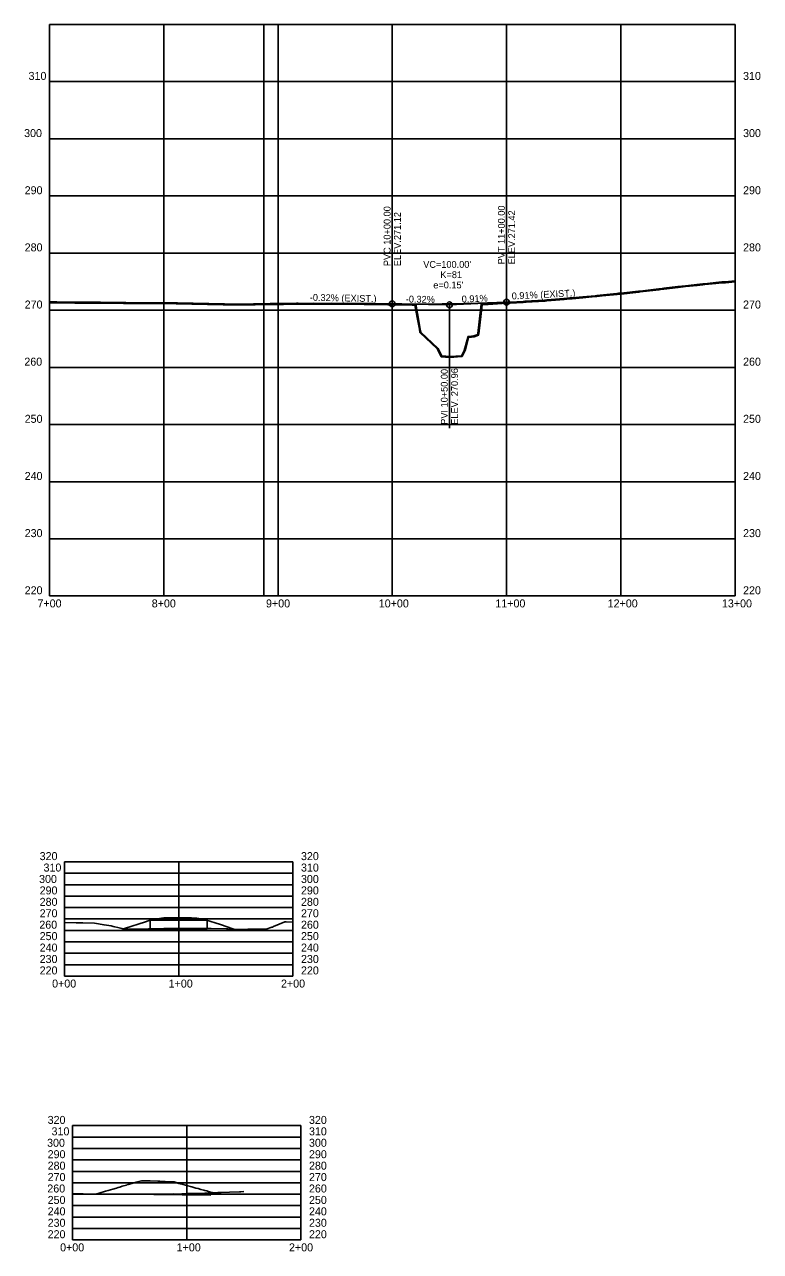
# Model space of a CAD drawing. Extents: x 1661035 to 1663788, y 668049 to 670894.
# Drawn here: x 1663144 to 1663788, y 669133 to 670207 of the extents above; entities that cross this region are included whole.
import ezdxf

# ---------------------------------------------------------------- set-up
doc = ezdxf.new("R2010")
doc.units = 0
for name, color, linetype in [('Default', 7, 'Continuous'), ('R_Axis', 7, 'Continuous'), ('R_Axis Annot', 7, 'Continuous'), ('R_Exist Surface', 7, 'Continuous'), ('R_Fin Surface', 7, 'Continuous'), ('R_Grid', 7, 'Continuous'), ('R_Horz Alg Annot', 7, 'Continuous'), ('R_Proposed Const Limits_Fill', 7, 'Continuous'), ('R_Vert Alg', 7, 'Continuous'), ('R_Vert Alg Annot', 7, 'Continuous'), ('R_Water', 7, 'Continuous')]:
    doc.layers.add(name, color=color, linetype=linetype)

msp = doc.modelspace()

# ---------------------------------------------------------------- linework, layer by layer
at = {"layer": 'Default'}
for p, q in [((1663600.6, 669965.7), (1663615.6, 669967)), ((1663165.4, 669964.1), (1663170.3, 669964)), ((1663170.3, 669964), (1663171.9, 669964)), ((1663171.9, 669964), (1663185.8, 669963.9)), ((1663185.8, 669963.9), (1663187.7, 669963.8)), ((1663187.7, 669963.8), (1663208.1, 669963.7)), ((1663208.1, 669963.7), (1663210, 669963.7)), ((1663210, 669963.7), (1663230.3, 669963.6)), ((1663230.3, 669963.6), (1663232.3, 669963.6)), ((1663232.3, 669963.6), (1663253.4, 669963.3)), ((1663253.4, 669963.3), (1663255.2, 669963.3)), ((1663255.2, 669963.3), (1663276.4, 669963.1)), ((1663276.4, 669963.1), (1663277.4, 669963.1)), ((1663277.4, 669963.1), (1663290, 669962.9)), ((1663290, 669962.9), (1663291.2, 669962.8)), ((1663291.2, 669962.8), (1663303.7, 669962.6)), ((1663303.7, 669962.6), (1663304.9, 669962.6)), ((1663304.9, 669962.6), (1663317.3, 669962.4)), ((1663317.3, 669962.4), (1663318.7, 669962.3)), ((1663318.7, 669962.3), (1663330.9, 669962.1)), ((1663330.9, 669962.1), (1663332.4, 669962.1)), ((1663332.4, 669962.1), (1663344, 669962.3)), ((1663344, 669962.3), (1663345.4, 669962.3)), ((1663345.4, 669962.3), (1663357, 669962.4)), ((1663357, 669962.4), (1663358.4, 669962.5)), ((1663358.4, 669962.5), (1663381.7, 669962.8)), ((1663381.7, 669962.8), (1663383.1, 669962.8)), ((1663383.1, 669962.8), (1663395.3, 669962.7)), ((1663395.3, 669962.7), (1663396.8, 669962.8)), ((1663396.8, 669962.8), (1663409, 669962.7)), ((1663409, 669962.7), (1663412, 669962.8)), ((1663412, 669962.8), (1663424.2, 669962.7)), ((1663424.2, 669962.7), (1663425.8, 669962.8)), ((1663425.8, 669962.8), (1663437.9, 669962.7)), ((1663437.9, 669962.7), (1663440.9, 669962.7)), ((1663440.9, 669962.7), (1663449.4, 669962.5)), ((1663449.4, 669962.5), (1663461.6, 669962.3)), ((1663461.6, 669962.3), (1663465.3, 669962.3)), ((1663465.3, 669962.3), (1663466.1, 669962.3)), ((1663466.1, 669962.3), (1663482.7, 669962)), ((1663482.7, 669962), (1663485.9, 669961.9)), ((1663485.9, 669961.9), (1663488.4, 669948.9)), ((1663540.3, 669936.3), (1663543.3, 669962)), ((1663543.3, 669962), (1663547.8, 669962.4)), ((1663547.8, 669962.4), (1663549.1, 669962.5)), ((1663549.1, 669962.5), (1663565.8, 669963.7)), ((1663565.8, 669963.7), (1663566.8, 669963.8)), ((1663566.8, 669963.8), (1663568.6, 669963.9)), ((1663568.6, 669963.9), (1663579.9, 669964.4)), ((1663579.9, 669964.4), (1663581.4, 669964.5)), ((1663581.4, 669964.5), (1663592.9, 669965.1)), ((1663592.9, 669965.1), (1663593.4, 669965.1)), ((1663593.4, 669965.1), (1663598.7, 669965.5)), ((1663598.7, 669965.5), (1663600.6, 669965.7)), ((1663488.4, 669948.9), (1663489.9, 669940.2)), ((1663489.9, 669940.2), (1663490.4, 669937.6)), ((1663490.4, 669937.6), (1663495.3, 669932.9)), ((1663532.5, 669933.7), (1663536.7, 669934.2)), ((1663536.7, 669934.2), (1663536.9, 669934.3)), ((1663536.9, 669934.3), (1663540.2, 669935.5)), ((1663540.2, 669935.5), (1663540.3, 669936.3)), ((1663495.3, 669932.9), (1663505.6, 669923.1)), ((1663528.3, 669921.5), (1663531.4, 669932.8)), ((1663531.4, 669932.8), (1663531.5, 669933.7)), ((1663531.5, 669933.7), (1663532.3, 669933.7)), ((1663532.3, 669933.7), (1663532.5, 669933.7)), ((1663505.6, 669923.1), (1663508.7, 669916.9)), ((1663508.7, 669916.9), (1663508.8, 669916.8)), ((1663508.8, 669916.8), (1663515.7, 669916.2)), ((1663515.7, 669916.2), (1663516.1, 669916.1)), ((1663516.1, 669916.1), (1663525.7, 669916.9)), ((1663525.7, 669916.9), (1663525.9, 669916.9)), ((1663525.9, 669916.9), (1663528.2, 669921.4)), ((1663528.2, 669921.4), (1663528.3, 669921.5))]:
    msp.add_line(p, q, dxfattribs=at)
msp.add_lwpolyline([(1663765.3, 669982.3), (1663757.1, 669981.7), (1663755.5, 669981.7), (1663753.9, 669981.5), (1663748.7, 669980.9), (1663738.7, 669979.9), (1663737.3, 669979.8), (1663732, 669979.2), (1663722, 669978.2), (1663715.4, 669977.4), (1663703, 669976), (1663701.5, 669975.8), (1663698.8, 669975.5), (1663682.3, 669973.5), (1663682.1, 669973.5), (1663681, 669973.4), (1663665.5, 669971.7), (1663663.3, 669971.5), (1663662, 669971.4), (1663644.4, 669969.5), (1663643, 669969.4), (1663632.3, 669968.5), (1663622.7, 669967.6), (1663620.9, 669967.5), (1663615.6, 669967)], dxfattribs=at)
at = {"layer": 'R_Axis'}
for p, q in [((1663165.4, 669706.7), (1663165.4, 670206.7)), ((1663165.4, 669706.7), (1663165.4, 670206.7)), ((1663765.4, 669706.7), (1663765.4, 670206.7)), ((1663165.4, 669706.7), (1663765.4, 669706.7)), ((1663178.5, 669374.1), (1663178.5, 669474.1)), ((1663378.5, 669374.1), (1663378.5, 669474.1)), ((1663178.5, 669374.1), (1663378.5, 669374.1)), ((1663185.5, 669143.3), (1663185.5, 669243.3)), ((1663385.5, 669143.3), (1663385.5, 669243.3)), ((1663185.5, 669143.3), (1663385.5, 669143.3))]:
    msp.add_line(p, q, dxfattribs=at)
at = {"layer": 'R_Exist Surface'}
for points in [[(1663165.4, 669963.2), (1663170.3, 669963.2), (1663171.8, 669963.1), (1663185.8, 669963.1), (1663187.6, 669963), (1663208.1, 669962.9), (1663210, 669962.8), (1663230.3, 669962.7), (1663232.3, 669962.7), (1663253.4, 669962.5), (1663255.2, 669962.5), (1663276.4, 669962.3), (1663277.4, 669962.2), (1663290, 669962), (1663291.2, 669962), (1663303.7, 669961.8), (1663304.9, 669961.7), (1663317.3, 669961.5), (1663318.7, 669961.5), (1663330.9, 669961.3), (1663332.4, 669961.3), (1663344, 669961.4), (1663345.4, 669961.5), (1663357, 669961.6), (1663358.4, 669961.6), (1663370.1, 669961.8), (1663381.7, 669961.9), (1663383.1, 669961.9), (1663395.3, 669961.9), (1663396.8, 669961.9), (1663409, 669961.9), (1663410.5, 669961.9), (1663412, 669961.9), (1663424.2, 669961.9), (1663425.8, 669961.9), (1663437.8, 669961.9), (1663440.9, 669961.8), (1663449.4, 669961.7), (1663461.5, 669961.5), (1663465.2, 669961.4), (1663466.1, 669961.4), (1663482.7, 669961.2), (1663485.2, 669961.1), (1663487.6, 669948.8), (1663489.1, 669940.1), (1663489.6, 669937.2), (1663494.7, 669932.3), (1663499.3, 669927.9), (1663505, 669922.6), (1663508, 669916.5), (1663508.3, 669916), (1663515.5, 669915.4), (1663515.9, 669915.3), (1663516, 669915.3), (1663525.7, 669916.1), (1663526.5, 669916.2), (1663529, 669921), (1663529.1, 669921.2), (1663532.2, 669932.7), (1663532.2, 669932.9), (1663532.3, 669932.9), (1663532.6, 669932.9), (1663536.9, 669933.4), (1663537.1, 669933.5), (1663541, 669934.9), (1663541.1, 669936.2), (1663544.1, 669961.3), (1663547.8, 669961.6), (1663549.2, 669961.7), (1663565.8, 669962.9), (1663566.9, 669962.9), (1663568.6, 669963), (1663579.9, 669963.6), (1663581.4, 669963.7), (1663582.5, 669963.7), (1663593, 669964.3), (1663593.4, 669964.3), (1663598.8, 669964.7), (1663599.1, 669964.7), (1663600.7, 669964.9), (1663615.7, 669966.2), (1663620.9, 669966.6), (1663622.8, 669966.8), (1663632.3, 669967.7), (1663643.1, 669968.6), (1663644.5, 669968.7), (1663649, 669969.2), (1663662.1, 669970.6), (1663663.4, 669970.7), (1663665.6, 669970.9), (1663681.1, 669972.6), (1663682.2, 669972.7), (1663682.4, 669972.7), (1663698.9, 669974.6), (1663701.6, 669975), (1663703.1, 669975.1), (1663715.5, 669976.6), (1663722.1, 669977.4), (1663732.1, 669978.4), (1663737.3, 669978.9), (1663738.8, 669979.1), (1663748.7, 669980.1), (1663754, 669980.7), (1663755.6, 669980.8), (1663757.1, 669980.8), (1663765.4, 669981.5)], [(1663178.5, 669421), (1663188.9, 669420.8), (1663194.5, 669420.7), (1663204.8, 669420.5), (1663204.8, 669420.5), (1663213.2, 669418.9), (1663219.4, 669418.2), (1663221.2, 669417.5), (1663222.5, 669417.2), (1663225.2, 669416.7), (1663228.7, 669415.7), (1663230.5, 669415.2), (1663240.7, 669415.3), (1663252.1, 669415.5), (1663253.3, 669415.5), (1663256.5, 669415.5), (1663265.4, 669415.8), (1663268, 669415.9), (1663278.9, 669415.9), (1663280.5, 669415.9), (1663292.4, 669415.9), (1663305.4, 669415.7), (1663306.9, 669415.7), (1663307, 669415.7), (1663320.3, 669415.4), (1663321.5, 669415.4), (1663326, 669415.3), (1663335.1, 669414.8), (1663339.1, 669415.2), (1663349.3, 669415.1), (1663355, 669415.1), (1663360.1, 669416.8), (1663360.7, 669417), (1663361.4, 669417.4), (1663361.4, 669417.4), (1663371.5, 669421.6), (1663371.9, 669421.6), (1663372, 669421.6), (1663372.4, 669421.6), (1663378.5, 669421.4)], [(1663185.5, 669183.7), (1663193.7, 669183.6), (1663194.9, 669183.6), (1663212, 669183.4), (1663213.1, 669183.4), (1663228, 669183.4), (1663234.4, 669183.4), (1663243.4, 669183.4), (1663243.8, 669183.4), (1663258.7, 669183.4), (1663259.8, 669183.4), (1663274, 669183.5), (1663275.8, 669183.4), (1663286.5, 669183.8), (1663288.4, 669183.8), (1663288.7, 669183.8), (1663301.5, 669184.3), (1663305.6, 669184.4), (1663312.8, 669184.7), (1663315.8, 669184.8), (1663323, 669185), (1663331.8, 669185.3), (1663332.5, 669185.3), (1663333, 669185.3), (1663335.5, 669185.7)]]:
    msp.add_lwpolyline(points, dxfattribs=at)
at = {"layer": 'R_Fin Surface'}
for points in [[(1663230.1, 669415.3), (1663230.2, 669415.4), (1663230.4, 669415.5), (1663231, 669415.7), (1663249.4, 669421.7), (1663249.5, 669421.7), (1663255.1, 669423.6), (1663255.4, 669423.6), (1663255.7, 669423.7), (1663259.6, 669424.3), (1663263.3, 669424.9), (1663265.6, 669425), (1663267.3, 669425.1), (1663275.8, 669425.2), (1663278.5, 669425.3), (1663280.3, 669425.2), (1663289.6, 669425), (1663289.7, 669425), (1663289.8, 669425), (1663293.4, 669424.9), (1663293.7, 669424.9), (1663294.4, 669424.8), (1663301.2, 669423.6), (1663301.4, 669423.6), (1663301.8, 669423.5), (1663315.2, 669419.2), (1663325.9, 669415.6), (1663328.2, 669414.9)], [(1663206.5, 669183.5), (1663206.7, 669183.6), (1663208.8, 669184.2), (1663214.4, 669185.9), (1663216.7, 669186.6), (1663218.9, 669187.2), (1663220.8, 669187.8), (1663224, 669188.7), (1663225.4, 669189.1), (1663227.1, 669189.6), (1663228.9, 669190.2), (1663232.8, 669191.3), (1663233, 669191.4), (1663234.4, 669191.8), (1663239.6, 669193.3), (1663241.3, 669193.8), (1663242.5, 669194.1), (1663246, 669195.1), (1663246.3, 669195.1), (1663246.8, 669195.1), (1663247.9, 669195.1), (1663248.3, 669195.1), (1663253.6, 669194.9), (1663260.1, 669194.6), (1663260.2, 669194.6), (1663260.2, 669194.6), (1663260.2, 669194.6), (1663262.1, 669194.6), (1663264.8, 669194.4), (1663266.6, 669194.4), (1663272, 669194.1), (1663272.7, 669194.1), (1663274.4, 669194), (1663276.4, 669193.5), (1663278.6, 669192.8), (1663278.8, 669192.8), (1663279.4, 669192.6), (1663279.6, 669192.6), (1663279.7, 669192.5), (1663282.4, 669191.8), (1663284.4, 669191.3), (1663285.3, 669191), (1663286.5, 669190.7), (1663288.7, 669190.1), (1663288.8, 669190), (1663289.9, 669189.7), (1663293.6, 669188.7), (1663295.2, 669188.3), (1663295.5, 669188.2), (1663295.6, 669188.2), (1663298, 669187.5), (1663300.4, 669186.9), (1663301.3, 669186.6), (1663303, 669186.2), (1663303.6, 669186), (1663305.4, 669185.5), (1663309.2, 669184.5)]]:
    msp.add_lwpolyline(points, dxfattribs=at)
at = {"layer": 'R_Grid'}
for p, q in [((1663165.4, 670206.7), (1663765.4, 670206.7)), ((1663165.4, 670206.7), (1663765.4, 670206.7)), ((1663265.4, 669706.7), (1663265.4, 670206.7)), ((1663365.4, 669706.7), (1663365.4, 670206.7)), ((1663465.4, 669706.7), (1663465.4, 670206.7)), ((1663565.4, 669706.7), (1663565.4, 670206.7)), ((1663665.4, 669706.7), (1663665.4, 670206.7)), ((1663165.4, 670156.7), (1663765.4, 670156.7)), ((1663165.4, 670106.7), (1663765.4, 670106.7)), ((1663165.4, 670056.7), (1663765.4, 670056.7)), ((1663165.4, 670006.7), (1663765.4, 670006.7)), ((1663165.4, 669956.7), (1663765.4, 669956.7)), ((1663165.4, 669906.7), (1663765.4, 669906.7)), ((1663165.4, 669856.7), (1663765.4, 669856.7)), ((1663165.4, 669806.7), (1663765.4, 669806.7)), ((1663165.4, 669756.7), (1663765.4, 669756.7)), ((1663178.5, 669474.1), (1663378.5, 669474.1)), ((1663178.5, 669474.1), (1663378.5, 669474.1)), ((1663278.5, 669374.1), (1663278.5, 669474.1)), ((1663178.5, 669464.1), (1663378.5, 669464.1)), ((1663178.5, 669454.1), (1663378.5, 669454.1)), ((1663178.5, 669444.1), (1663378.5, 669444.1)), ((1663178.5, 669434.1), (1663378.5, 669434.1)), ((1663178.5, 669424.1), (1663378.5, 669424.1)), ((1663178.5, 669414.1), (1663378.5, 669414.1)), ((1663178.5, 669404.1), (1663378.5, 669404.1)), ((1663178.5, 669394.1), (1663378.5, 669394.1)), ((1663178.5, 669384.1), (1663378.5, 669384.1)), ((1663185.5, 669243.3), (1663385.5, 669243.3)), ((1663185.5, 669243.3), (1663385.5, 669243.3)), ((1663285.5, 669143.3), (1663285.5, 669243.3)), ((1663185.5, 669233.3), (1663385.5, 669233.3)), ((1663185.5, 669223.3), (1663385.5, 669223.3)), ((1663185.5, 669213.3), (1663385.5, 669213.3)), ((1663185.5, 669203.3), (1663385.5, 669203.3)), ((1663185.5, 669193.3), (1663385.5, 669193.3)), ((1663185.5, 669183.3), (1663385.5, 669183.3)), ((1663185.5, 669173.3), (1663385.5, 669173.3)), ((1663185.5, 669163.3), (1663385.5, 669163.3)), ((1663185.5, 669153.3), (1663385.5, 669153.3))]:
    msp.add_line(p, q, dxfattribs=at)
at = {"layer": 'R_Proposed Const Limits_Fill'}
msp.add_line((1663306.5, 669182.5), (1663206.5, 669183.5), dxfattribs=at)
at = {"layer": 'R_Vert Alg'}
for p, q in [((1663460.4, 669962.4), (1663515.4, 669961.5)), ((1663515.4, 669961.5), (1663540.4, 669962.6))]:
    msp.add_line(p, q, dxfattribs=at)
msp.add_lwpolyline([(1663465.4, 669962.3), (1663467.5, 669962.2), (1663469.5, 669962.2), (1663471.6, 669962.2), (1663473.7, 669962.2), (1663475.8, 669962.1), (1663477.9, 669962.1), (1663480, 669962.1), (1663482, 669962.1), (1663484.1, 669962.1), (1663486.2, 669962.1), (1663488.3, 669962.1), (1663490.4, 669962.1), (1663492.5, 669962.1), (1663494.5, 669962.1), (1663496.6, 669962.1), (1663498.7, 669962.1), (1663500.8, 669962.1), (1663502.9, 669962.1), (1663505, 669962.1), (1663507, 669962.1), (1663509.1, 669962.2), (1663511.2, 669962.2), (1663513.3, 669962.2), (1663517.5, 669962.3), (1663519.5, 669962.3), (1663521.6, 669962.3), (1663523.7, 669962.4), (1663525.8, 669962.4), (1663527.9, 669962.5), (1663530, 669962.5), (1663532, 669962.6), (1663534.1, 669962.6), (1663536.2, 669962.7), (1663538.3, 669962.7), (1663540.4, 669962.8), (1663542.5, 669962.9), (1663544.5, 669962.9), (1663546.6, 669963), (1663548.7, 669963.1), (1663550.8, 669963.2), (1663552.9, 669963.2), (1663555, 669963.3), (1663557, 669963.4), (1663559.1, 669963.5), (1663561.2, 669963.6), (1663563.3, 669963.7), (1663565.4, 669963.8)], dxfattribs=at)
at = {"layer": 'R_Vert Alg Annot'}
for p, q in [((1663465.4, 669992.3), (1663465.4, 670070.3)), ((1663565.4, 669993.8), (1663565.4, 670071.8)), ((1663465.4, 669962.3), (1663465.4, 669992.3)), ((1663565.4, 669963.8), (1663565.4, 669993.8)), ((1663515.4, 669961.5), (1663515.4, 669931.5)), ((1663515.4, 669931.5), (1663515.4, 669853.5))]:
    msp.add_line(p, q, dxfattribs=at)
for centre in [(1663465.4, 669962.3), (1663515.4, 669961.5), (1663565.4, 669963.8)]:
    msp.add_circle(centre, 2.5, dxfattribs=at)
at = {"layer": 'R_Water'}
for p, q in [((1663353, 669706.7), (1663353, 670206.7)), ((1663253.5, 669423.2), (1663253.5, 669423.4)), ((1663253.5, 669423.4), (1663254.5, 669423.4)), ((1663253.5, 669415.2), (1663253.5, 669423.4)), ((1663254.5, 669423.2), (1663254.5, 669423.4)), ((1663254.5, 669423.2), (1663302.5, 669423.2)), ((1663302.5, 669423.4), (1663303.5, 669423.4)), ((1663302.5, 669423.2), (1663302.5, 669423.4)), ((1663303.5, 669423.2), (1663303.5, 669423.4)), ((1663303.5, 669415.2), (1663303.5, 669423.4)), ((1663253.5, 669415.2), (1663303.5, 669415.2))]:
    msp.add_line(p, q, dxfattribs=at)

# ---------------------------------------------------------------- texts
at = {"layer": 'R_Axis Annot'}
for s, height, p in [('310', 7, (1663147.1, 670158.2)), ('310', 7, (1663772.4, 670158.2)), ('300', 7, (1663143.2, 670108.2)), ('300', 7, (1663772.4, 670108.2)), ('290', 7, (1663143.7, 670058.2)), ('290', 7, (1663772.4, 670058.2)), ('280', 7, (1663143.7, 670008.2)), ('280', 7, (1663772.4, 670008.2)), ('270', 7, (1663143.7, 669958.2)), ('270', 7, (1663772.4, 669958.2)), ('260', 7, (1663143.4, 669908.2)), ('260', 7, (1663772.4, 669908.2)), ('250', 7, (1663143.7, 669858.2)), ('250', 7, (1663772.4, 669858.2)), ('240', 7, (1663143.7, 669808.2)), ('240', 7, (1663772.4, 669808.2)), ('230', 7, (1663143.7, 669758.2)), ('230', 7, (1663772.4, 669758.2)), ('220', 7, (1663143.7, 669708.2)), ('220', 7, (1663772.4, 669708.2)), ('7+00', 7, (1663154.9, 669696.7)), ('-', 0.0001, (1663165.4, 669706.7)), ('8+00', 7, (1663254.9, 669696.7)), ('9+00', 7, (1663354.9, 669696.7)), ('10+00', 7, (1663453.6, 669696.7)), ('11+00', 7, (1663555.6, 669696.7)), ('12+00', 7, (1663653.9, 669696.7)), ('13+00', 7, (1663753.9, 669696.7)), ('320', 7, (1663156.8, 669475.6)), ('320', 7, (1663156.8, 669475.6)), ('310', 7, (1663160.2, 669465.6)), ('320', 7, (1663385.5, 669475.6)), ('320', 7, (1663385.5, 669475.6)), ('310', 7, (1663385.5, 669465.6)), ('300', 7, (1663156.3, 669455.6)), ('300', 7, (1663385.5, 669455.6)), ('290', 7, (1663156.8, 669445.6)), ('290', 7, (1663385.5, 669445.6)), ('280', 7, (1663156.8, 669435.6)), ('280', 7, (1663385.5, 669435.6)), ('270', 7, (1663156.8, 669425.6)), ('270', 7, (1663385.5, 669425.6)), ('260', 7, (1663156.5, 669415.6)), ('260', 7, (1663385.5, 669415.6)), ('250', 7, (1663156.8, 669405.6)), ('250', 7, (1663385.5, 669405.6)), ('240', 7, (1663156.8, 669395.6)), ('240', 7, (1663385.5, 669395.6)), ('230', 7, (1663156.8, 669385.6)), ('230', 7, (1663385.5, 669385.6)), ('220', 7, (1663156.8, 669375.6)), ('220', 7, (1663385.5, 669375.6)), ('0+00', 7, (1663167.7, 669364.1)), ('-', 0.0001, (1663178.5, 669374.1)), ('1+00', 7, (1663269.7, 669364.1)), ('2+00', 7, (1663368, 669364.1)), ('320', 7, (1663163.8, 669244.8)), ('320', 7, (1663163.8, 669244.8)), ('320', 7, (1663392.5, 669244.8)), ('320', 7, (1663392.5, 669244.8)), ('310', 7, (1663167.2, 669234.8)), ('310', 7, (1663392.5, 669234.8)), ('300', 7, (1663163.3, 669224.8)), ('300', 7, (1663392.5, 669224.8)), ('290', 7, (1663163.8, 669214.8)), ('290', 7, (1663392.5, 669214.8)), ('280', 7, (1663163.8, 669204.8)), ('280', 7, (1663392.5, 669204.8)), ('270', 7, (1663163.8, 669194.8)), ('270', 7, (1663392.5, 669194.8)), ('260', 7, (1663163.5, 669184.8)), ('260', 7, (1663392.5, 669184.8)), ('250', 7, (1663163.8, 669174.8)), ('250', 7, (1663392.5, 669174.8)), ('240', 7, (1663163.8, 669164.8)), ('230', 7, (1663163.8, 669154.8)), ('240', 7, (1663392.5, 669164.8)), ('230', 7, (1663392.5, 669154.8)), ('220', 7, (1663163.8, 669144.8)), ('220', 7, (1663392.5, 669144.8)), ('0+00', 7, (1663174.7, 669133.3)), ('-', 0.0001, (1663185.5, 669143.3)), ('1+00', 7, (1663276.7, 669133.3)), ('2+00', 7, (1663375, 669133.3))]:
    msp.add_text(s, height=height, dxfattribs=at).set_placement(p)
at = {"layer": 'R_Horz Alg Annot'}
for s, rotation, p in [('-0.32% (EXIST.)', 358.8667, (1663393.2, 669965)), ('-0.32%', 359.0833, (1663477.2, 669963.5)), ('0.91%', 2.6052, (1663526.3, 669963.4)), ('0.91% (EXIST.)', 2.9048, (1663570.1, 669966.1))]:
    msp.add_text(s, height=6, rotation=rotation, dxfattribs=at).set_placement(p)
at = {"layer": 'R_Vert Alg Annot'}
for s, p in [('PVC 10+00.00', (1663463.9, 669995.3)), ('ELEV.271.12', (1663472.9, 669995.3)), ('PVT 11+00.00', (1663563.9, 669996.8)), ('ELEV.271.42', (1663572.9, 669996.8)), ('PVI 10+50.00', (1663513.9, 669856.5)), ('ELEV. 270.96', (1663522.9, 669856.5))]:
    msp.add_text(s, height=6, rotation=90, dxfattribs=at).set_placement(p)
for s, p in [("VC=100.00'", (1663492.5, 669993.8)), ('K=81', (1663507.5, 669984.8)), ("e=0.15'", (1663501.3, 669975.8))]:
    msp.add_text(s, height=6, dxfattribs=at).set_placement(p)

doc.saveas('drawing.dxf')
